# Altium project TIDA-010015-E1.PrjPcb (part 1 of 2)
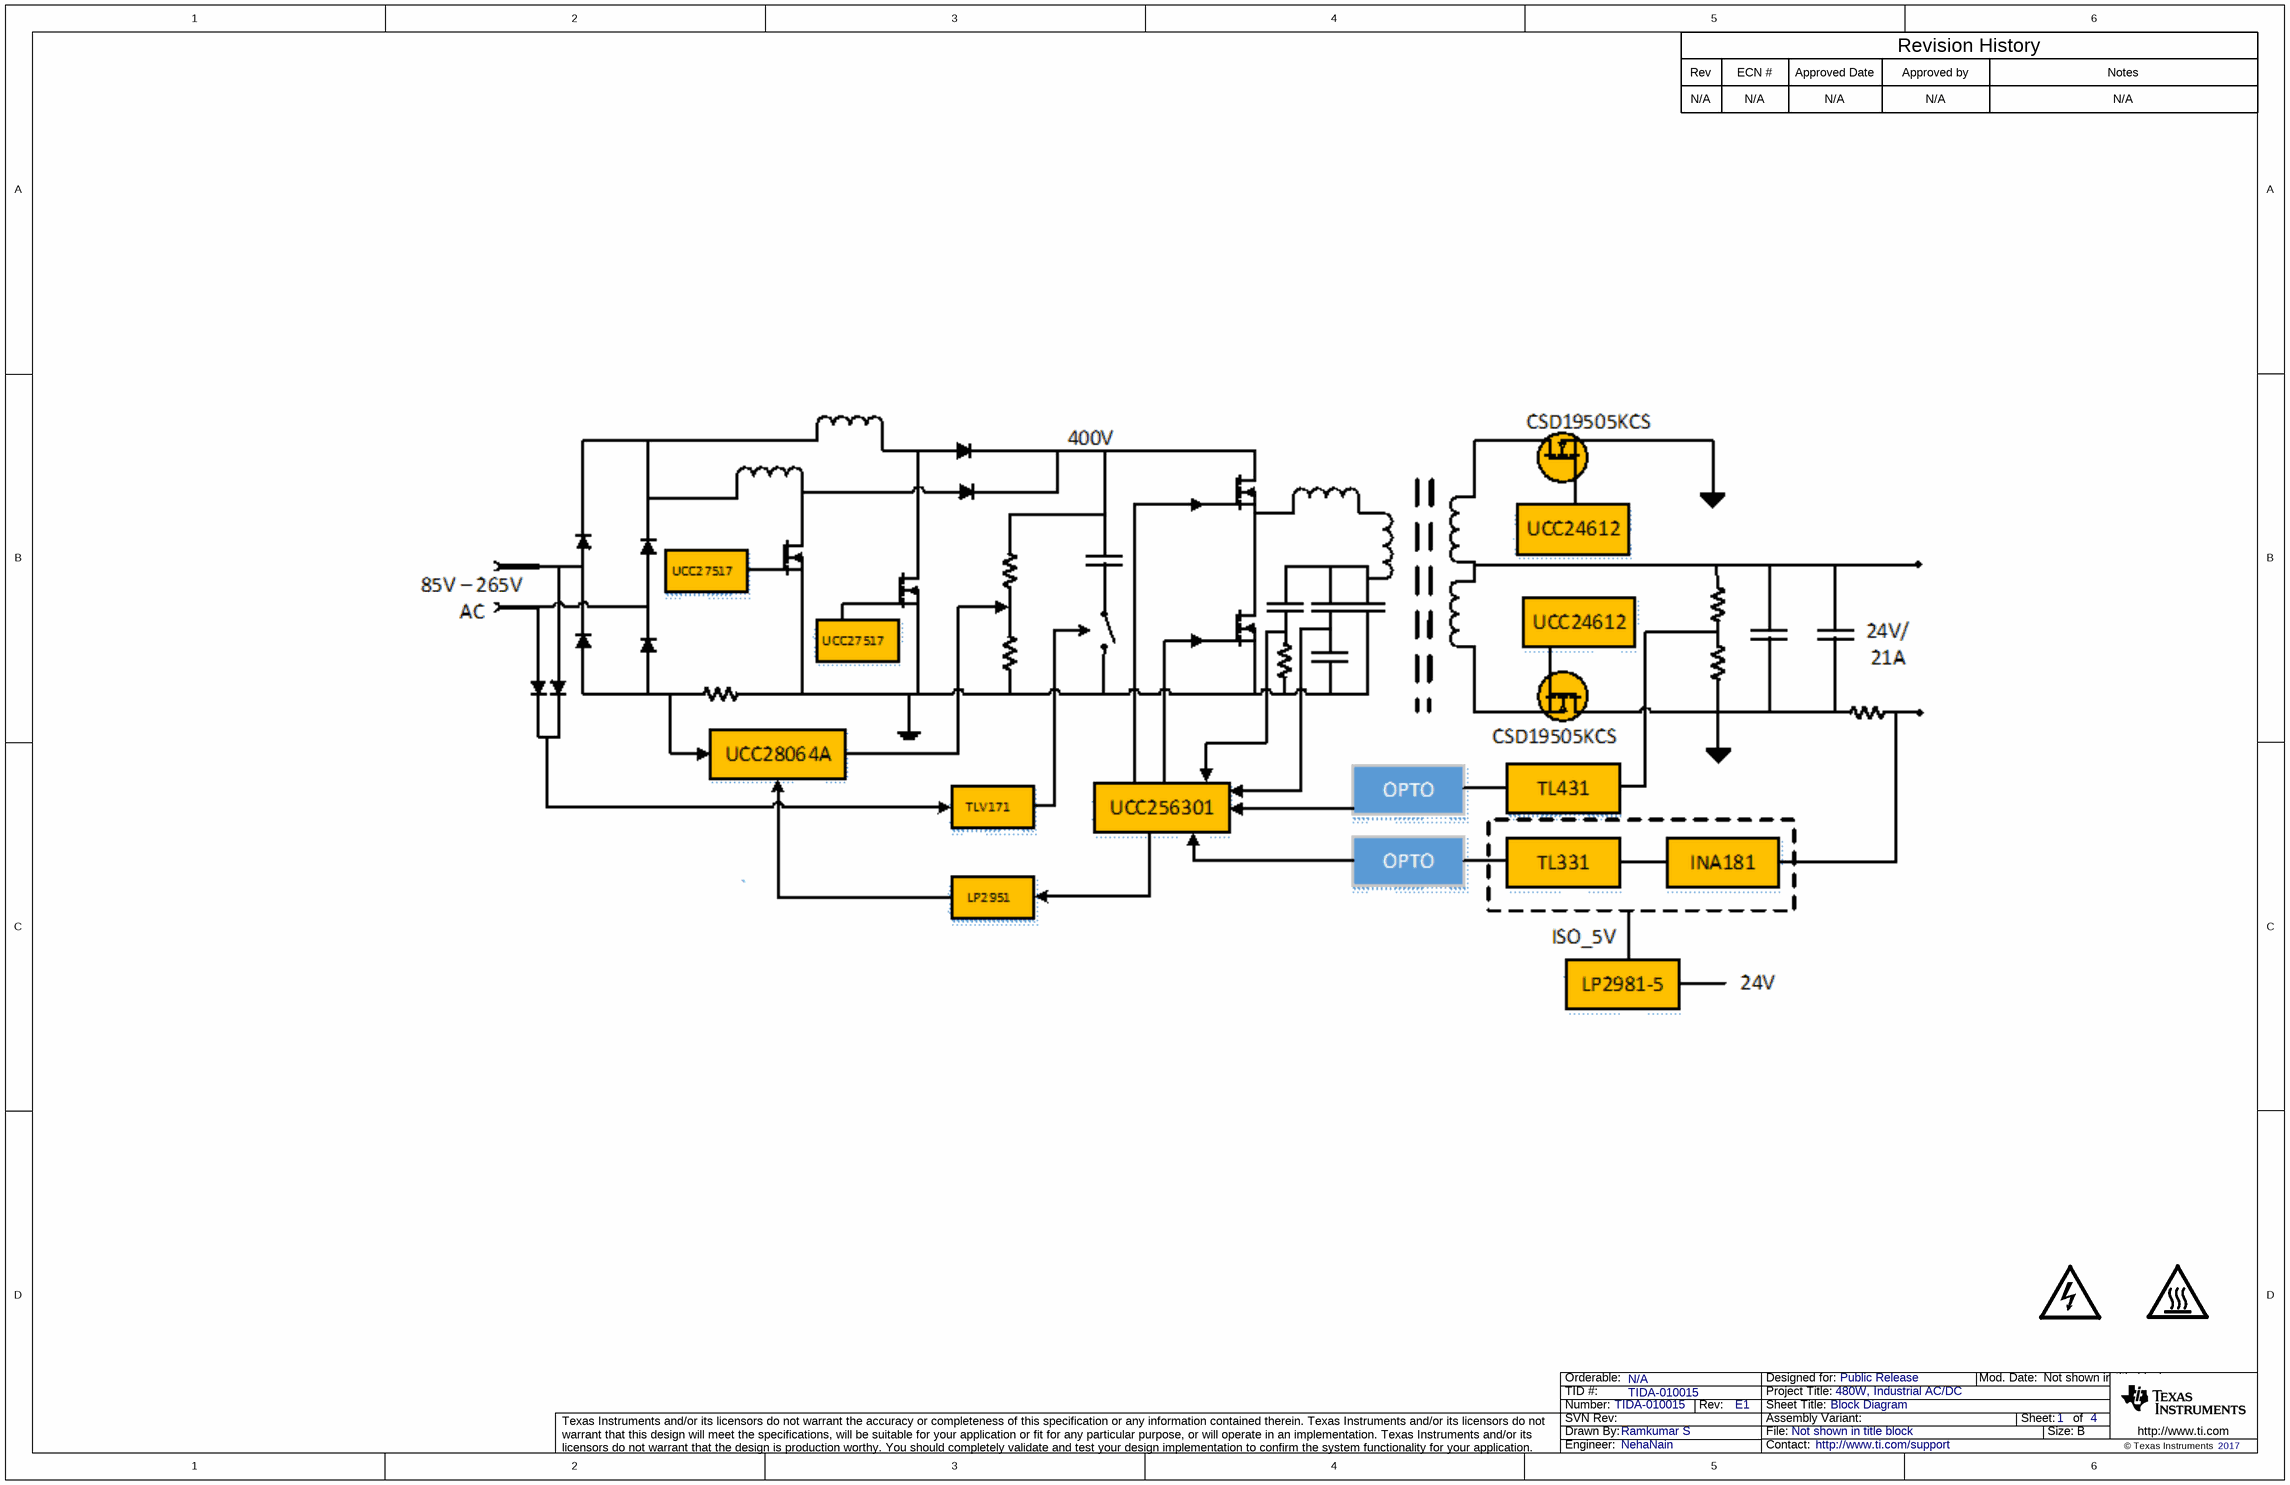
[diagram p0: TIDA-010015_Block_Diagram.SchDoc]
CopyrightYear: 2017; EVM_orderable: N/A; PCB_Layout: Koteswara Rao; PCB_Rev: E1; PRJ_Customer: Public Release; PRJ_Engineer: NehaNain; PRJ_Number: TIDA-010015; PRJ_Title: 480W, Industrial AC/DC; SCH_Rev: E1; TechSupport: http://www.ti.com/support; TID: TIDA-010015
4 sheets, 240 parts. Net scope: global (net labels, ports and power ports of the same name join across sheets).
Board file: TIDA-010015_PCB.PcbDoc
Sheets:
  TIDA-010015_Block_Diagram.SchDoc
  TIDA-010015_PFC.SchDoc
  TIDA-010015-LLC.SchDoc
  TIDA-010015_Hardware.SchDoc

## Sheet TIDA-010015_Block_Diagram.SchDoc: Block Diagram
size 431 x 279 mm; Date: Not shown in title block; ApprovedBy: Not shown in title block; CheckedBy: Not shown in title block; Author: Not shown in title block; CompanyName: Not shown in title block; DrawnBy: Ramkumar S; Engineer: Ramkumar S; Organization: Not shown in title block; Address1: Not shown in title block; Address2: Not shown in title block; Address3: Not shown in title block; Address4: Not shown in title block; DocumentNumber: 1; Revision: Use project parameter SCH_Rev; SheetNumber: 1; SheetTotal: 4; PageSetup: Record=PageOptions¦CenterHorizontal=True¦CenterVertical=True¦PrintScale=1.00¦XCorrection=1.00¦YCorrection=1.00¦PrintKind=0¦BorderSize=5000000¦LeftOffset=0¦BottomOffset=0¦Orientation=2¦PaperLength=1000¦PaperWidth=1000¦Scale=100¦PaperSource=15¦PrintQuality=600¦MediaType=1¦DitherType=10¦PaperKind=Letter¦PrintScaleMode=1

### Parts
(Parts that share a designator on the sheet are numbered #1, #2 ... from top to bottom, then left to right.)
LOGO?#1  DANGER HIGH VOLTAGE  [IEC_HighVoltage_Small]  (value not drawn)  (graphical)
LOGO?#2  CAUTION HOT SURFACE  [IEC_HotSurface_Small]  (value not drawn)  (graphical)

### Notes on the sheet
- Rev
- N/A
- ECN #
- Approved Date
- Approved by
- Revision History
- Notes

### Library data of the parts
LOGO?#1 = IEC_HighVoltage: IEC 61010-1 High Voltage Warning; SymbolCreator: a0412235
LOGO?#2 = IEC_HotSurface: IEC 61010-1 Hot Surface Warning; SymbolCreator: a0412235

## Sheet TIDA-010015_PFC.SchDoc: PFC
size 431 x 279 mm; Date: Not shown in title block; ApprovedBy: Not shown in title block; CheckedBy: Not shown in title block; Author: Not shown in title block; CompanyName: Not shown in title block; DrawnBy: Ramkumar S; Engineer: Ramkumar S; Organization: Not shown in title block; Address1: Not shown in title block; Address2: Not shown in title block; Address3: Not shown in title block; Address4: Not shown in title block; DocumentNumber: 1; Revision: Use project parameter SCH_Rev; SheetNumber: 2; SheetTotal: 4; PageSetup: Record=PageOptions¦CenterHorizontal=True¦CenterVertical=True¦PrintScale=1.00¦XCorrection=1.00¦YCorrection=1.00¦PrintKind=0¦BorderSize=5000000¦LeftOffset=0¦BottomOffset=0¦Orientation=2¦PaperLength=1000¦PaperWidth=1000¦Scale=100¦PaperSource=15¦PrintQuality=600¦MediaType=1¦DitherType=10¦PaperKind=Letter¦PrintScaleMode=1
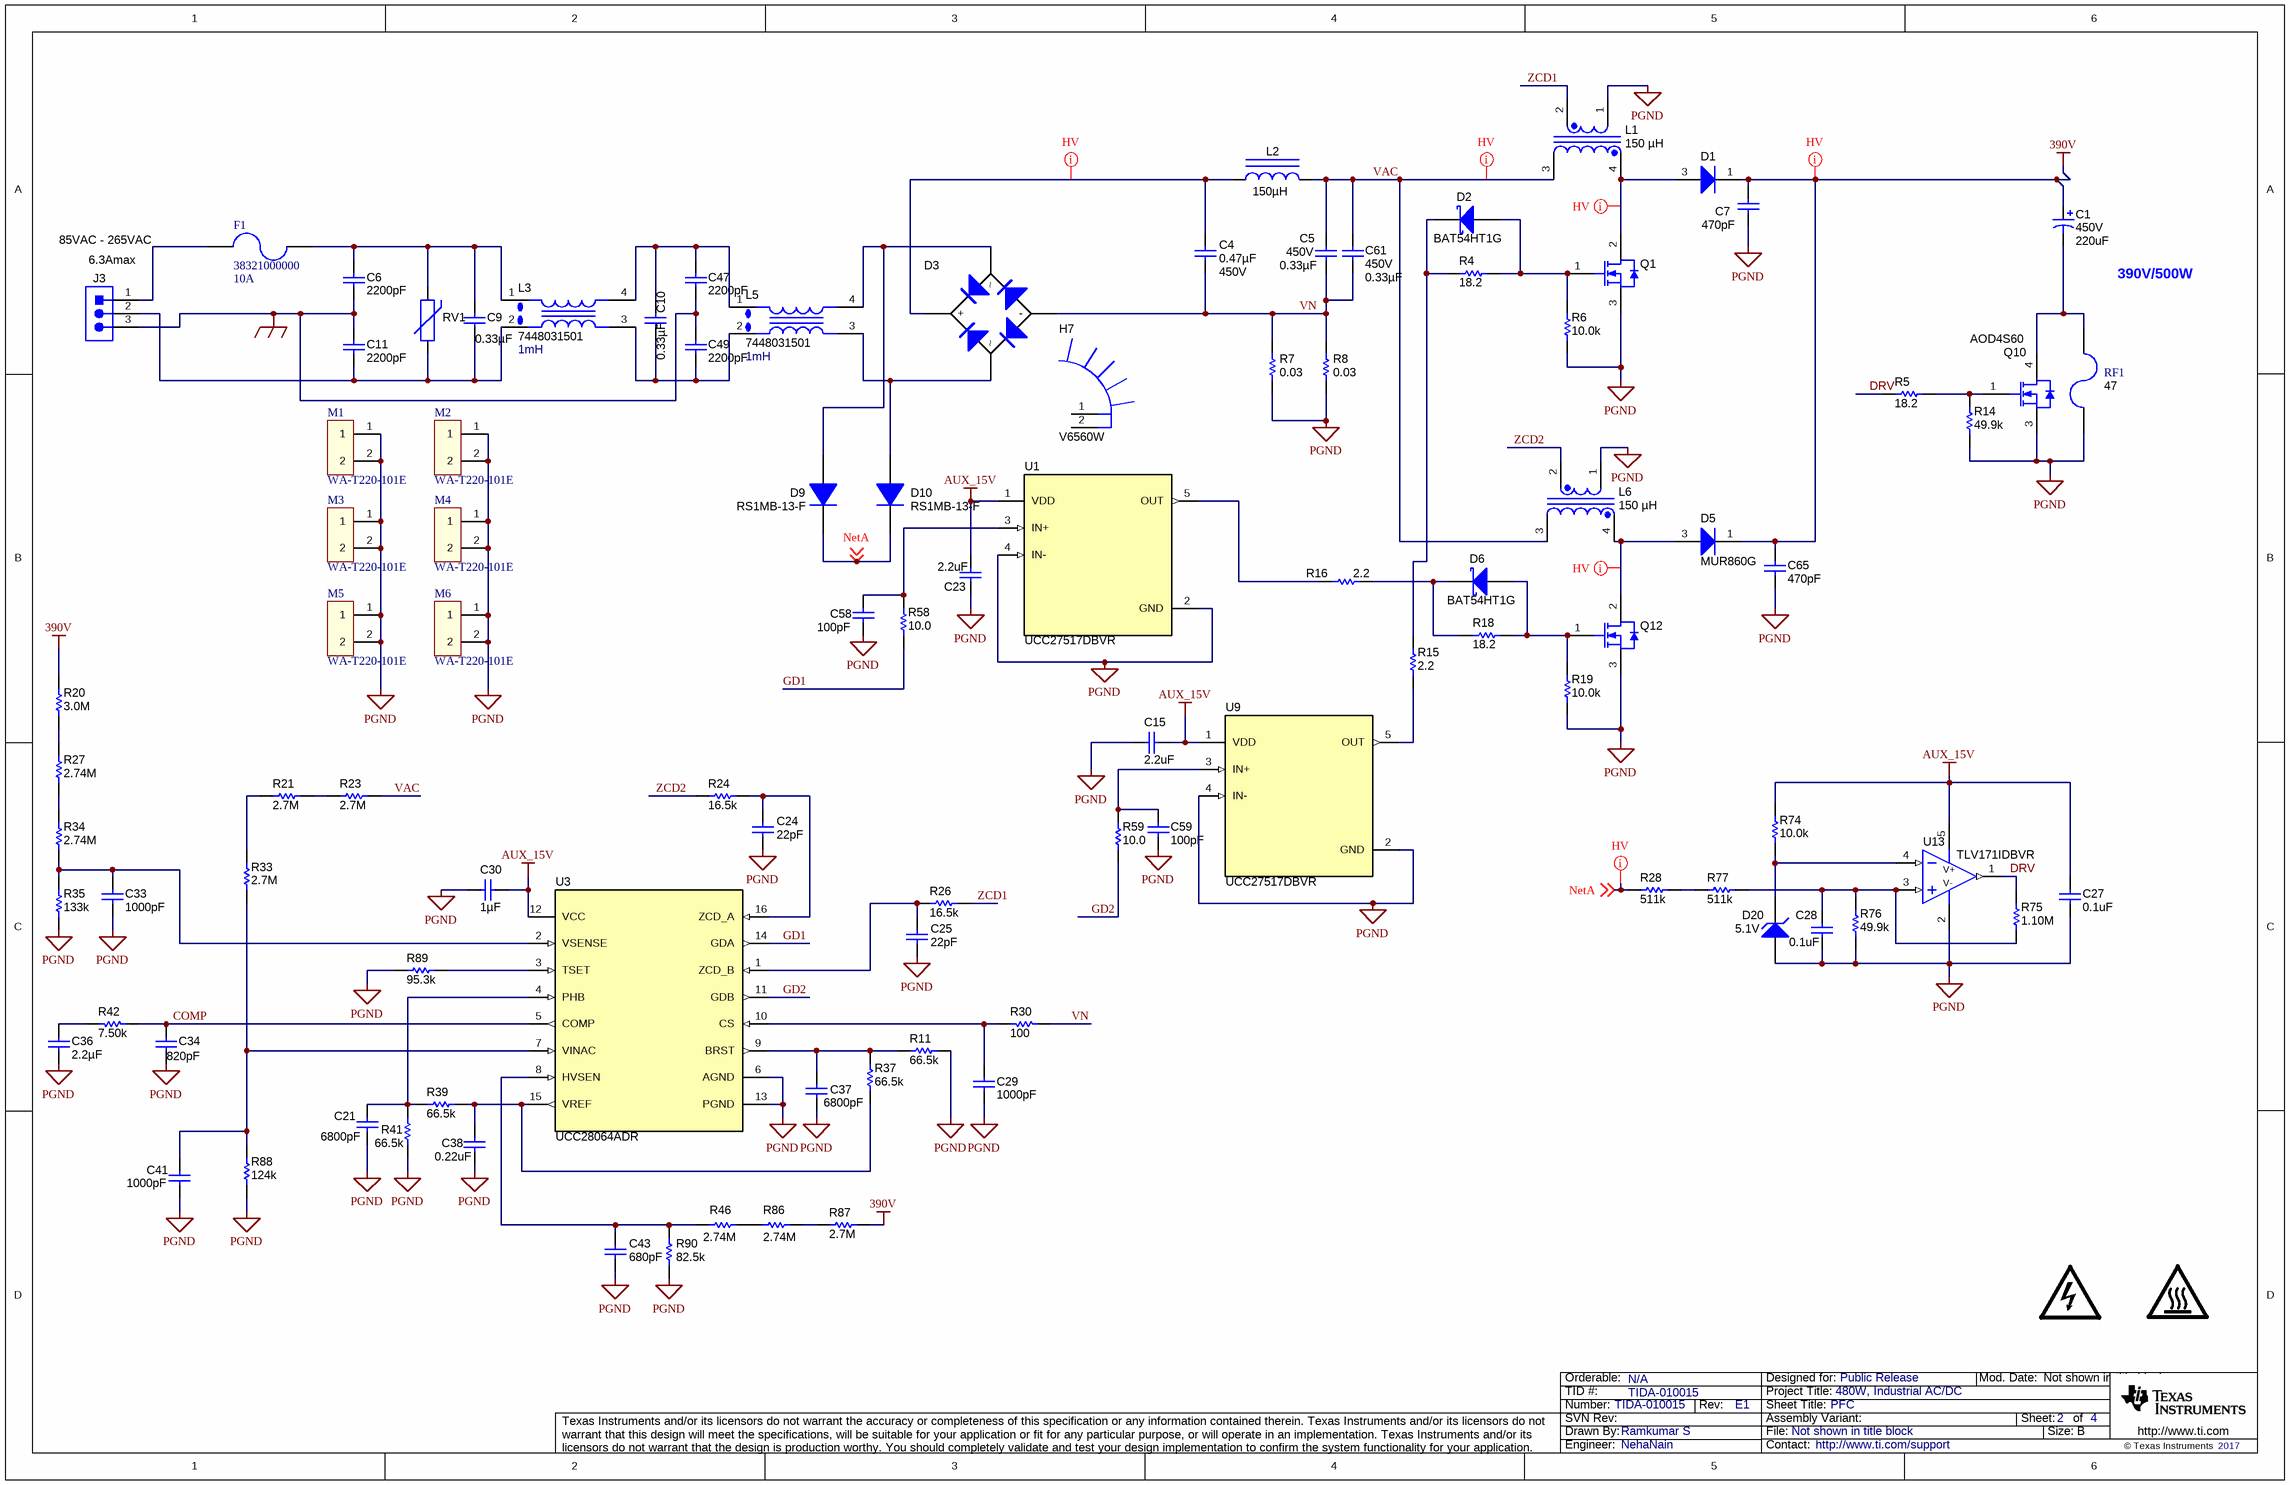
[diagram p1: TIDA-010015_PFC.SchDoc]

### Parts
(Parts that share a designator on the sheet are numbered #1, #2 ... from top to bottom, then left to right.)
C1  VDC_V: 450V  ValueDisplayed: 220uF  [SMQ_2540x2500]  (hidden comment: ESMR451VSN221MQ30S)
C4  ValueDisplayed: 0.47µF  Value2: 450V  [MPK_1800x650]  (hidden comment: 450MPK474J)
C5  VDC_V: 450V  ValueDisplayed: 0.33µF  [R46_1300x1200x600]  (hidden comment: ECW-FE2W334K)
C6  ValueDisplayed: 2200pF  [CD45_700x600x1100]  (hidden comment: AY2222M35Y5US63L7)
C7  ValueDisplayed: 470pF  [1210]  (hidden comment: VJ1210Y471KXEAT5Z)
C9  ValueDisplayed: 0.33µF  [B32922_14.5mm]  (hidden comment: B32922C3334K)
C10  ValueDisplayed: 0.33µF  [B32922_14.5mm]  (hidden comment: B32922C3334K)
C11  ValueDisplayed: 2200pF  [CD45_700x600x1100]  (hidden comment: AY2222M35Y5US63L7)
C15  ValueDisplayed: 2.2uF  [0805_150]  (hidden comment: 08053C225KAT2A)
C21  ValueDisplayed: 6800pF  [0603]  (hidden comment: GRM188R71E682KA01D)
C23  ValueDisplayed: 2.2uF  [0805_150]  (hidden comment: 08053C225KAT2A)
C24  ValueDisplayed: 22pF  [0603]  (hidden comment: C0603C220J5GACTU)
C25  ValueDisplayed: 22pF  [0603]  (hidden comment: C0603C220J5GACTU)
C27  ValueDisplayed: 0.1uF  [0603]  (hidden comment: C0603C104J3RACTU)
C28  ValueDisplayed: 0.1uF  [0603]  (hidden comment: C0603C104J3RACTU)
C29  ValueDisplayed: 1000pF  [0603]  (hidden comment: C1608X7R1H102K)
C30  ValueDisplayed: 1µF  [0603]  (hidden comment: GRM188R71E105KA12D)
C33  ValueDisplayed: 1000pF  [0603]  (hidden comment: C1608X7R1H102K)
C34  ValueDisplayed: 820pF  [0603]  (hidden comment: 06035A821JAT2A)
C36  ValueDisplayed: 2.2µF  [0805_HV]  (hidden comment: 0805YD225KAT2A)
C37  ValueDisplayed: 6800pF  [0603]  (hidden comment: GRM188R71E682KA01D)
C38  ValueDisplayed: 0.22uF  [0603]  (hidden comment: GRM188R71H224KAC4D)
C41  ValueDisplayed: 1000pF  [0603]  (hidden comment: 06031C102MAT2A)
C43  ValueDisplayed: 680pF  [0603]  (hidden comment: GRM188R71H681KA01D)
C47  ValueDisplayed: 2200pF  [CD45_700x600x1100]  (hidden comment: AY2222M35Y5US63L7)
C49  ValueDisplayed: 2200pF  [CD45_700x600x1100]  (hidden comment: AY2222M35Y5US63L7)
C58  ValueDisplayed: 100pF  [0805_HV1]  (hidden comment: 08055A101JAT2A)
C59  ValueDisplayed: 100pF  [0805_HV1]  (hidden comment: 08055A101JAT2A)
C61  VDC_V: 450V  ValueDisplayed: 0.33µF  [R46_1300x1200x600]  (hidden comment: ECW-FE2W334K)
C65  ValueDisplayed: 470pF  [1210]  (hidden comment: VJ1210Y471KXEAT5Z)
D1  MUR860G  [TO-220AC]  (value not drawn)
D2  BAT54HT1G  [sod-323]
D3  GBU2510-G  [GBU]  (value not drawn)
D5  MUR860G  [TO-220AC]
D6  BAT54HT1G  [sod-323]
D9  RS1MB-13-F  [SMB]
D10  RS1MB-13-F  [SMB]
D20  value 5.1V  [SOD-323]  (hidden comment: BZT52C5V1S-7-F)
F1  38321000000  value 10A  [FUSE_38321000000]
H7  V6560W  [ASMN_V6560X]
J3  350429-1  [TE_350429-1]  (value not drawn)
L1  value 150 µH  [IND_PQ2625]  (hidden comment: Custom)
L2  ValueDisplayed: 150µH  [IND_7447076]  (hidden comment: 7447076)
L3  7448031501  value 1mH  [WURTH_7448031501]
L5  7448031501  value 1mH  [WURTH_7448031501]
L6  value 150 µH  [IND_PQ2625]  (hidden comment: Custom)
LOGO?#3  DANGER HIGH VOLTAGE  [IEC_HighVoltage_Small]  (value not drawn)  (graphical)
LOGO?#4  CAUTION HOT SURFACE  [IEC_HotSurface_Small]  (value not drawn)  (graphical)
M1  WA-T220-101E  [HEATSINK_WA-T220-101E]
M2  WA-T220-101E  [HEATSINK_WA-T220-101E]
M3  WA-T220-101E  [HEATSINK_WA-T220-101E]
M4  WA-T220-101E  [HEATSINK_WA-T220-101E]
M5  WA-T220-101E  [HEATSINK_WA-T220-101E]
M6  WA-T220-101E  [HEATSINK_WA-T220-101E]
Q1  IPP60R190P6  [TO-220AB]  (value not drawn)
Q10  AOD4S60  [DPAK]
Q12  IPP60R190P6  [TO-220AB]  (value not drawn)
R4  ValueDisplayed: 18.2  [0805_HV1]  (hidden comment: CRCW080518R2FKEA)
R5  ValueDisplayed: 18.2  [0805_HV1]  (hidden comment: CRCW080518R2FKEA)
R6  ValueDisplayed: 10.0k  [0805_HV]  (hidden comment: CRCW080510K0FKEA)
R7  ValueDisplayed: 0.03  [2512]  (hidden comment: CSRN2512FK30L0)
R8  ValueDisplayed: 0.03  [2512]  (hidden comment: CSRN2512FK30L0)
R11  ValueDisplayed: 66.5k  [0603]  (hidden comment: CRCW060366K5FKEA)
R14  ValueDisplayed: 49.9k  [0603]  (hidden comment: ERJ-3EKF4992V)
R15  ValueDisplayed: 2.2  [0805_HV1]  (hidden comment: CRCW08052R20JNEA)
R16  ValueDisplayed: 2.2  [0805_HV1]  (hidden comment: CRCW08052R20JNEA)
R18  ValueDisplayed: 18.2  [0805_HV1]  (hidden comment: CRCW080518R2FKEA)
R19  ValueDisplayed: 10.0k  [0805_HV]  (hidden comment: CRCW080510K0FKEA)
R20  ValueDisplayed: 3.0M  [1206]  (hidden comment: CRCW12063M00JNEA)
R21  ValueDisplayed: 2.7M  [1206]  (hidden comment: CRCW12062M70JNEA)
R23  ValueDisplayed: 2.7M  [1206]  (hidden comment: CRCW12062M70JNEA)
R24  ValueDisplayed: 16.5k  [0603]  (hidden comment: CRCW060316K5FKEA)
R26  ValueDisplayed: 16.5k  [0603]  (hidden comment: CRCW060316K5FKEA)
R27  ValueDisplayed: 2.74M  [0805_HV]  (hidden comment: CRCW08052M74FKEA)
R28  value 511k  [1206]  (hidden comment: CRCW1206511KFKEA)
R30  ValueDisplayed: 100  [0603]  (hidden comment: CRCW0603100RFKEA)
R33  ValueDisplayed: 2.7M  [1206]  (hidden comment: CRCW12062M70JNEA)
R34  ValueDisplayed: 2.74M  [0805_HV]  (hidden comment: CRCW08052M74FKEA)
R35  ValueDisplayed: 133k  [0603]  (hidden comment: CRCW0603133KFKEA)
R37  ValueDisplayed: 66.5k  [0603]  (hidden comment: CRCW060366K5FKEA)
R39  ValueDisplayed: 66.5k  [0603]  (hidden comment: CRCW060366K5FKEA)
R41  ValueDisplayed: 66.5k  [0603]  (hidden comment: CRCW060366K5FKEA)
R42  ValueDisplayed: 7.50k  [0603]  (hidden comment: CRCW06037K50FKEA)
R46  ValueDisplayed: 2.74M  [0805_HV]  (hidden comment: CRCW08052M74FKEA)
R58  ValueDisplayed: 10.0  [0603]  (hidden comment: CRCW060310R0FKEAHP)
R59  ValueDisplayed: 10.0  [0603]  (hidden comment: CRCW060310R0FKEAHP)
R74  ValueDisplayed: 10.0k  [0805_HV]  (hidden comment: CRCW080510K0FKEA)
R75  ValueDisplayed: 1.10M  [0603]  (hidden comment: CRCW06031M10FKEA)
R76  value 49.9k  [1206]  (hidden comment: CRCW120649K9FKEA)
R77  value 511k  [1206]  (hidden comment: CRCW1206511KFKEA)
R86  ValueDisplayed: 2.74M  [0805_HV]  (hidden comment: CRCW08052M74FKEA)
R87  ValueDisplayed: 2.7M  [1206]  (hidden comment: CRCW12062M70JNEA)
R88  ValueDisplayed: 124k  [0603]  (hidden comment: ERJ-3EKF1243V)
R89  ValueDisplayed: 95.3k  [0603]  (hidden comment: CRCW060395K3FKEA)
R90  ValueDisplayed: 82.5k  [0603]  (hidden comment: CRCW060382K5FKEA)
RF1  ValueDisplayed: 47  [RESADV550W80L2600D750B]  (hidden comment: EMC2-47RKI)
RV1  S10K275E2  [VAR_S10K275E2]  (value not drawn)
U1  UCC27517DBVR  [DBV0005A_N]
U3  PartNumber: UCC28064ADR  [D0016A_N]  (hidden comment: UCC28064DR)
U9  UCC27517DBVR  [DBV0005A_N]
U13  TLV171IDBVR  [DBV0005A_N]

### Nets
390V: C1.1(+) C7.1 C65.1 D1.1(K) D5.1(K) R20.2 R87.2
AUX_15V: C15.2 C23.1 C27.1 C30.2 R74.2 U1.1(VDD) U3.12(VCC) U9.1(VDD) U13.5(V+)
EARTH: C6.2 C11.1 C47.2 C49.1 J3.3
PGND: C7.2 C15.1 C21.2 C23.2 C24.2 C25.2 C27.2 C28.2 C29.2 C30.1 C33.2 C34.2 C36.2 C37.2 C38.2 C41.2 C43.2 C58.2 C59.2 C65.2 D20.2(A) L1.1 L6.1 M1.1 M1.2 M2.1 M2.2 M3.1 M3.2 M4.1 M4.2 M5.1 M5.2 M6.1 M6.2 Q1.3(S) Q10.3(S) Q12.3(S) R6.1 R7.1 R8.1 R11.2 R14.2 R19.1 R35.1 R41.2 R76.1 R88.2 R89.1 R90.1 RF1.1 U1.2(GND) U1.4(IN-) U3.6(AGND) U3.13(PGND) U9.2(GND) U9.4(IN-) U13.2(V-)
COMP: C34.1 R42.1 U3.5(COMP)
DRV: R5.2 R75.2 U13.1(OUT)
GD1: R58.1 U3.14(GDA)
GD2: R59.1 U3.11(GDB)
NetA: D9.1(K) D10.1(K) R28.1 ; off-sheet NetA
VAC: C5.1 C61.1 L1.3 L2.2 L6.3 R23.2
VN: C4.2 C5.2 C61.2 D3.4(-) R7.2 R8.2 R30.1
ZCD1: L1.2 R26.2
ZCD2: L6.2 R24.1
NetC1_2: C1.2(-) Q10.4(D) RF1.2
NetC4_1: C4.1 D3.1(+) L2.1
NetC6_1: C6.1 C9.1 F1.2 L3.1 RV1.2
NetC9_2: C9.2 C11.2 J3.2 L3.2 RV1.1
NetC10_1: C10.1 C47.1 L3.4 L5.1
NetC10_2: C10.2 C49.2 L3.3 L5.2
NetC21_1: C21.1 R39.1 R41.1 U3.4(PHB)
NetC24_1: C24.1 R24.2 U3.16(ZCD_A)
NetC25_1: C25.1 R26.1 U3.1(ZCD_B)
NetC28_1: C28.1 R75.1 R76.2 R77.2 U13.3(IN+)
NetC29_1: C29.1 R30.2 U3.10(CS)
NetC33_1: C33.1 R34.1 R35.2 U3.2(VSENSE)
NetC36_1: C36.1 R42.2
NetC37_1: C37.1 R11.1 R37.2 U3.9(BRST)
NetC38_1: C38.1 R37.1 R39.2 U3.15(VREF)
NetC41_1: C41.1 R33.2 R88.1 U3.7(VINAC)
NetC43_1: C43.1 R46.1 R90.2 U3.8(HVSEN)
NetC58_1: C58.1 R58.2 U1.3(IN+)
NetC59_1: C59.1 R59.2 U9.3(IN+)
NetD1_3: D1.3(A) L1.4 Q1.2(D)
NetD2_1: D2.1(K) R4.1 R15.2
NetD2_2: D2.2(A) Q1.1(G) R4.2 R6.2
NetD3_2: D3.2 D9.2(A) L5.4
NetD3_3: D3.3 D10.2(A) L5.3
NetD5_3: D5.3(A) L6.4 Q12.2(D)
NetD6_1: D6.1(K) R16.2 R18.1
NetD6_2: D6.2(A) Q12.1(G) R18.2 R19.2
NetD20_1: D20.1(K) R74.1 U13.4(IN-)
NetF1_1: F1.1 J3.1
NetQ10_1: Q10.1(G) R5.1 R14.1
NetR15_1: R15.1 U9.5(OUT)
NetR16_1: R16.1 U1.5(OUT)
NetR20_1: R20.1 R27.2
NetR21_1: R21.1 R33.1
NetR21_2: R21.2 R23.1
NetR27_1: R27.1 R34.2
NetR28_2: R28.2 R77.1
NetR46_2: R46.2 R86.1
NetR86_2: R86.2 R87.1
NetR89_2: R89.2 U3.3(TSET)

Not connected (* = marked no-connect by the designer): H7 1 2

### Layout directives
net class HV: 390V, NetA, NetC4_1, NetD1_3, NetD5_3, VAC

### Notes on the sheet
- 85VAC - 265VAC
- (near J3) 6.3Amax
- 390V/500W

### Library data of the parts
C1 = CMP-0010055-2: CAP ALUM 220UF 20% 450V SNAP; Manufacturer: Chemi-Con; TaMin_C: -25°C; Polarized: Y; Value1: Unknown; U/M: EA; TaMax_C: 85°C; SizeZ_mm: 27; SizeX_mm: 25.4; Cap_Case: 25.4x25mm; CompType: Capacitor; Cap_F: 220µF
C4 = 450MPK474J: CAP, Film, 0.47 µF, 450 V, +/- 5%, TH; Manufacturer: Rubycon; Polarized: N; CompType: Capacitor; Value: 0.47uF; U/M: EA; Cap_F: 0.00000047; Tolerance_%: 5; Value1: Unknown; VDC_V: 450; TaMin_C: -40; TaMax_C: 105; Cap_Case: 18x6.5mm; AEC Category: Q200
C5 C61 = CMP-0012558-3: 0.33µF Film Capacitor 450V Polypropylene (PP), Metallized Radial; Manufacturer: Panasonic Electronic Components; TaMin_C: -40°C; Polarized: N; SizeAreaWB_mm2: 120; Value1: Unknown; TaMax_C: 110°C; Tolerance_%: 10%; SizeZ_mm: 12.1; SizeX_mm: 13; SizeY_mm: 6; Cap_Case: 13x12x6; SizeArea_mm2: 78; AEC Category: Q200
C6 C11 C47 C49 = AY2222M35Y5US63L7: CAP, CERM, 2200 pF, 300 V, +/- 20%, Y5U, AEC-Q200 Grade 1, D9.5xT5mm; Manufacturer: Vishay-Bccomponents; Polarized: N; CompType: Capacitor; Value: 2200pF; U/M: EA; Cap_F: 0.0000000022; Tolerance_%: 20; Value1: Unknown; VDC_V: 300; Value2: 300V; TaMin_C: -55; TaMax_C: 125; Cap_Case: 9.5x5mm; SizeArea_mm2: 47.5; SizeAreaWB_mm2: 80.5; SizeX_mm: 9.5; SizeY_mm: 5; SizeZ_mm: 14.5; AEC Category: Q200; AEC Qualified: Y; AEC Grade: 1
C7 C65 = VJ1210Y471KXEAT5Z: CAP, CERM, 470 pF, 500 V, +/- 10%, X7R, 1210; Manufacturer: Vishay-Vitramon; Polarized: N; CompType: Capacitor; Value: 470pF; U/M: EA; Cap_F: 0.00000000047; Tolerance_%: 10; Value1: Unknown; VDC_V: 500; Value2: 500V; TaMin_C: -55; TaMax_C: 125; SizeArea_mm2: 8; SizeAreaWB_mm2: 14.7; SizeX_mm: 3.2; SizeY_mm: 2.5; SizeZ_mm: 1.35; AEC Category: Q200
C9 C10 = B32922C3334K: CAP, Film, 0.33 µF, X2 305 VAC, +/- 10%, TH; Manufacturer: TDK; Polarized: N; CompType: Capacitor; Value: 0.33uF; U/M: EA; Cap_F: 0.00000033; Tolerance_%: 10; TaMin_C: -40; TaMax_C: 110; Cap_Case: 18x8x14.5mm; SizeAreaWB_mm2: 210; SizeArea_mm2: 153; SizeX_mm: 18; SizeY_mm: 8.5; SizeZ_mm: 14.5; AEC Category: Q200; VAC_X: 305
C15 C23 = CMP-0007573-2: CAP, CERM, 2.2 uF, 25 V, +/- 10%, X7R, 0805; Manufacturer: AVX; TaMin_C: -55°C; Polarized: N; SizeAreaWB_mm2: 6.75; Value1: Unknown; U/M: EA; Value: 2.2uF; TaMax_C: 125°C; SizeZ_mm: 1.5; SizeX_mm: 2; SizeY_mm: 1.25; Cap_Case: 0805; Value2: 25V; SizeArea_mm2: 2.5; CompType: Capacitor; Cap_F: 2.2µF; AEC Category: Q200
C21 C37 = CMP-0007427-4: CAP, CERM, 6800 pF, 25 V, +/- 10%, X7R, 0603; Manufacturer: MuRata; TaMin_C: -55°C; Polarized: N; SizeAreaWB_mm2: 4.68; Value1: Unknown; U/M: EA; Value: 6800pF; TaMax_C: 125°C; SizeZ_mm: 1; SizeX_mm: 1.6; SizeY_mm: 0.8; Value2: 25V; SizeArea_mm2: 1.28; CompType: Capacitor; Cap_F: 6.8nF; AEC Category: Q200
C24 C25 = C0603C220J5GACTU: CAP, CERM, 22 pF, 50 V, +/- 5%, C0G/NP0, 0603; Manufacturer: Kemet; Polarized: N; CompType: Capacitor; Value: 22pF; U/M: EA; Cap_F: 0.000000000022; Tolerance_%: 5; Value1: Unknown; VDC_V: 50; Value2: 50V; TaMin_C: -55; TaMax_C: 125
C27 C28 = CMP-0006856-5: CAP, CERM, 0.1 uF, 25 V, +/- 5%, X7R, 0603; Manufacturer: Kemet; TaMin_C: -55°C; Polarized: N; SizeAreaWB_mm2: 4.68; Value1: Unknown; U/M: EA; Value: 0.1uF; TaMax_C: 125°C; SizeZ_mm: 1; SizeX_mm: 1.6; SizeY_mm: 0.8; Value2: 25V; SizeArea_mm2: 1.28; CompType: Capacitor; Cap_F: 100nF; AEC Category: Q200
C29 C33 = C1608X7R1H102K: CAP, CERM, 1000 pF, 50 V, +/- 10%, X7R, 0603; Manufacturer: TDK; Polarized: N; CompType: Capacitor; Value: 1000pF; U/M: EA; Cap_F: 0.000000001; Tolerance_%: 10; ESR_ohm: 0.24; Value1: 0.24 ohm; VDC_V: 50; Value2: 50V; TaMin_C: -55; TaMax_C: 125
C30 = GRM188R71E105KA12D: CAP, CERM, 1 µF, 25 V, +/- 10%, X7R, 0603; Manufacturer: MuRata; Polarized: N; CompType: Capacitor; Value: 1uF; U/M: EA; Cap_F: 0.000001; Tolerance_%: 10; Value1: Unknown; VDC_V: 25; Value2: 25V; TaMin_C: -55; TaMax_C: 125
C34 = 06035A821JAT2A: CAP, CERM, 820 pF, 50 V, +/- 5%, C0G/NP0, 0603; Manufacturer: AVX; Polarized: N; CompType: Capacitor; Value: 820pF; U/M: EA; Cap_F: 0.00000000082; Tolerance_%: 5; ESR_ohm: 0.052; Value1: 0.052 ohm; VDC_V: 50; Value2: 50V; TaMin_C: -55; TaMax_C: 125
C36 = 0805YD225KAT2A: CAP, CERM, 2.2 µF, 16 V, +/- 10%, X5R, 0805; Manufacturer: AVX; Polarized: N; CompType: Capacitor; Value: 2.2uF; U/M: EA; Cap_F: 0.0000022; Tolerance_%: 10; ESR_ohm: 0.009; Value1: 0.009 ohm; VDC_V: 16; Value2: 16V; TaMin_C: -55; TaMax_C: 85; Cap_Case: 0805
C38 = CMP-0007445-4: CAP, CERM, 0.22 uF, 50 V, +/- 10%, X7R, 0603; Manufacturer: MuRata; TaMin_C: -55°C; Polarized: N; SizeAreaWB_mm2: 4.68; Value1: Unknown; U/M: EA; Value: 0.22uF; TaMax_C: 125°C; SizeZ_mm: 1; SizeX_mm: 1.6; SizeY_mm: 0.8; Value2: 50V; SizeArea_mm2: 1.28; CompType: Capacitor; Cap_F: 220nF; AEC Category: Q200
C41 = 06031C102MAT2A: CAP, CERM, 1000 pF, 100 V, +/- 20%, X7R, 0603; Manufacturer: AVX; Polarized: N; CompType: Capacitor; Value: 1000pF; U/M: EA; Cap_F: 0.000000001; Tolerance_%: 20; ESR_ohm: 0.276; Value1: 0.276 ohm; VDC_V: 100; Value2: 100V; TaMin_C: -55; TaMax_C: 125
C43 = GRM188R71H681KA01D: CAP, CERM, 680 pF, 50 V, +/- 10%, X7R, 0603; Manufacturer: MuRata; Polarized: N; CompType: Capacitor; Value: 680pF; U/M: EA; Cap_F: 0.00000000068; Tolerance_%: 10; Value1: Unknown; VDC_V: 50; Value2: 50V; TaMin_C: -55; TaMax_C: 125
C58 C59 = 08055A101JAT2A: CAP, CERM, 100 pF, 50 V,+/- 5%, C0G/NP0, 0805; Manufacturer: AVX; Polarized: N; CompType: Capacitor; Value: 100pF; U/M: EA; Cap_F: 0.0000000001; Tolerance_%: 5; ESR_ohm: 0.356; Value1: 0.356 ohm; VDC_V: 50; Value2: 50V; TaMin_C: -55; TaMax_C: 125; Cap_Case: 0805; SizeArea_mm2: 2.5; SizeAreaWB_mm2: 6.75; SizeX_mm: 2; SizeY_mm: 1.25; SizeZ_mm: 1.45; AEC Category: Q200; Green_Lifecycle: Active; Green_REACh: Passed
D1 D5 = CMP-0029037-1: Diode, Ultrafast, 600 V, 8 A, TH; Manufacturer: ON Semiconductor; Io_A: 8A; Green_Lifecycle: Not Set; SizeAreaWB_mm2: 78.975; Vr_V: 600V; Green_REACh: Incomplete; TJmax_C: 175°C; U/M: EA; Value: 600V; SizeZ_mm: 23; SizeX_mm: 10.15; SizeY_mm: 4.5; Vf_V: 9.8dV; Value2: 0.98V; SizeArea_mm2: 45.675; AEC Category: Q101; RJC_CperW: 4.75
D2 D6 = BAT54HT1G: Diode, Schottky, 30V, 0.2A, SOD-323; Manufacturer: ON Semiconductor; Value: 0.35V; U/M: EA; Vf_V: 0.35; Io_A: 0.2; Vr_V: 30
D3 = GBU4A-BP: RECT BRIDGE GPP 1000V 25A GBU; Manufacturer: Comchip Technology; CompType: Diode; U/M: EA; Vf_V: 0.95; Io_A: 4; Value1: 8A; Vr_V: 50; Value2: 50V; TJmax_C: 150; RJC_CperW: 2.2; Type: Switching-Bridge
D9 D10 = RS1MB-13-F: Diode, P-N, 1000 V, 1 A, SMB; Manufacturer: Diodes Inc.; U/M: EA; Vf_V: 1.3; Value: 1000V; Value1: 1A; Value2: 1.3V; Io_A: 1; Vr_V: 1000; TJmax_C: 150; RJC_CperW: 20; SizeAreaWB_mm2: 44.156; SizeArea_mm2: 21.336; SizeX_mm: 5.6; SizeY_mm: 3.81; SizeZ_mm: 2.6; AEC Category: Q101; Green_Lifecycle: Active; Green_REACh: Passed
D20 = CMP-0005865-1: Diode, Zener, 5.1 V, 200 mW, SOD-323; Manufacturer: Diodes Inc.; Power_W: 200mW; SizeAreaWB_mm2: 8.695; Value1: 0.2W; RJA_CperW: 625; U/M: EA; SizeZ_mm: 1; SizeX_mm: 2.7; SizeY_mm: 1.35; SizeArea_mm2: 3.645; AEC Category: Q101
F1 = 38321000000: FUSE, BOARD MOUNT, 10 A, 300 V, TH-2P; Manufacturer: LITTELFUSE INC; SymbolCreator: x0199378
H7 = CMP-0004065-1: HEATSINK, ALUM, ANOD, for TO-220; Manufacturer: Assman WSW
J3 = 350429-1: Header(Shrouded), 6.35mm, 3x1, Tin, TH; Manufacturer: TE Connectivity; SymbolCreator: a0799628; U/M: EA
L1 L6 = PFC4124QM-161K06D-00: Transformer, 160 uH, TH; SymbolCreator: Altium; U/M: EA
L2 = 7447020: Inductor, Toroid, Powdered Iron, 150 µH, 5A, TH; Manufacturer: Wurth Elektronik; Value: 150uH; Value1: 0.16 ohm
L3 L5 = 7448031501: FILTER, WE-CMBNC COMMON MODE POWER LINE CHOKE, 1mH, 15A, VERTICAL, TH-4P; Manufacturer: Wurth Elektronics; SymbolCreator: x0199378
LOGO?#3 = IEC_HighVoltage: as LOGO?#1 on sheet TIDA-010015_Block_Diagram
LOGO?#4 = IEC_HotSurface: as LOGO?#2 on sheet TIDA-010015_Block_Diagram
M1-M6 = WA-T220-101E: HEATSINK, ALUMINIUM WITH CLIP, VERTICAL MOUNT, SOLDERABLE PIN, TO-220; Manufacturer: OHMITE; SymbolCreator: x0199378
Q1 Q12 = CMP-0001223-3: MOSFET N-CHANNEL 600V 26A TO220; PartNumber: IPA60R120P7XKSA1; Alternate Manufacturer: None; Manufacturer: Infineon Technologies; SizeZ_mm: 19.4; ChType: N; Value2: 37 nC; VdsMax_V: 650V; SizeX_mm: 10.2; SizeY_mm: 4.5; Vgs_V: 20V; QgTyp_nC: 37; Value: 650V; SizeArea_mm2: 45.9; AEC Category: Q101; IdsMax_A: 20.2A; SizeAreaWB_mm2: 79.3; U/M: EA
Q10 = CMP-0001138-3: MOSFET, N-CH, 600 V, 4 A, DPAK; Alternate Manufacturer: None; Manufacturer: AOS; SizeZ_mm: 2.29; ChType: N; Value2: 6 nC; VdsMax_V: 600V; SizeX_mm: 9.91; SizeAreaWB_mm2: 101.7114; SizeY_mm: 6.54; Vgs_V: 30V; QgTyp_nC: 6; Value: 600V; SizeArea_mm2: 64.8114; AEC Category: Q101; IdsMax_A: 4A; U/M: EA
R4 R5 R18 = CRCW080518R2FKEA: RES, 18.2, 1%, 0.125 W, 0805; Manufacturer: Vishay-Dale; CompType: Resistor; Value: 18.2; Value_Code: 18R2; Tolerance_%: 1; Power_W: 0.125; Value2: 0.125W; VDC_V: 150; TempCo: 100 ppm/C; SizeArea_mm2: 2.5; SizeX_mm: 2; SizeY_mm: 1.25; SizeZ_mm: 1.45; EIA_Code: E96; U/M: EA; AEC Category: Q200
R6 R19 R74 = CRCW080510K0FKEA: RES, 10.0 k, 1%, 0.125 W, 0805; Manufacturer: Vishay-Dale; CompType: Resistor; Value: 10.0k; Res_ohm: 10000; Value_Code: 10k0; Tolerance_%: 1; Power_W: 0.125; Value2: 0.125W; VDC_V: 150; TempCo: 100 ppm/C; EIA_Code: E96; U/M: EA
R7 R8 = CSRN2512FK30L0: RES, 0.03, 1%, 2 W, 2512; Manufacturer: Stackpole Electronics Inc; CompType: Resistor; Value: 0.03; Value_Code: R030; Tolerance_%: 1; Power_W: 2; Value2: 2W; TempCo: 200 ppm/C; SizeArea_mm2: 20.16; SizeX_mm: 6.3; SizeY_mm: 3.2; SizeZ_mm: 0.71; EIA_Code: E96; U/M: EA; AEC Category: Q200
R11 R37 R39 R41 = CRCW060366K5FKEA: RES, 66.5 k, 1%, 0.1 W, 0603; Manufacturer: Vishay-Dale; CompType: Resistor; Value: 66.5k; Res_ohm: 66500; Value_Code: 66k5; Tolerance_%: 1; Power_W: 0.1; Value2: 0.1W; VDC_V: 75; TempCo: 100 ppm/C; EIA_Code: E96; U/M: EA
R14 = CMP-0022705-3: RES, 49.9 k, 1%, 0.1 W, AEC-Q200 Grade 0, 0603; Manufacturer: Panasonic; Power_W: 100mW; TempCo: 100 ppm/C; Value_Code: 49k9; U/M: EA; Value: 49.9k; EIA_Code: E96; SizeX_mm: 1.6; SizeY_mm: 0.8; SizeZ_mm: 1; Value2: 0.1W; SizeArea_mm2: 1.28; AEC Qualified: Y; VDC_V: 75V; AEC Grade: 0; AEC Category: Q200
R15 R16 = CRCW08052R20JNEA: RES, 2.2, 5%, 0.125 W, 0805; Manufacturer: Vishay-Dale; CompType: Resistor; Value: 2.2; Value_Code: 2R20; Tolerance_%: 5; Power_W: 0.125; Value2: 0.125W; VDC_V: 150; TempCo: 200 ppm/C; SizeArea_mm2: 2.5; SizeX_mm: 2; SizeY_mm: 1.25; SizeZ_mm: 1.45; EIA_Code: E24; U/M: EA; AEC Category: Q200; Green_Lifecycle: Active; Green_REACh: Passed
R20 = CMP-0018672-3: RES, 3.0 M, 5%, 0.25 W, AEC-Q200 Grade 0, 1206; Manufacturer: Vishay-Dale; Power_W: 250mW; TempCo: 200 ppm/C; Value_Code: 3M00; Value: 3.0Meg; EIA_Code: E24; Res_ohm: 3M; SizeX_mm: 3.2; SizeY_mm: 1.6; SizeZ_mm: 1.35; Value2: 0.25W; SizeArea_mm2: 5.12; AEC Qualified: Y; VDC_V: 200V; AEC Category: Q200; AEC Grade: 0
R21 R23 R33 R87 = CMP-0018647-3: RES, 2.7 M, 5%, 0.25 W, AEC-Q200 Grade 0, 1206; Manufacturer: Vishay-Dale; Power_W: 250mW; TempCo: 200 ppm/C; Value_Code: 2M70; Value: 2.7Meg; EIA_Code: E24; SizeX_mm: 3.2; SizeY_mm: 1.6; SizeZ_mm: 1.35; Value2: 0.25W; SizeArea_mm2: 5.12; AEC Qualified: Y; VDC_V: 200V; AEC Category: Q200; AEC Grade: 0
R24 R26 = CRCW060316K5FKEA: RES, 16.5 k, 1%, 0.1 W, 0603; Manufacturer: Vishay-Dale; CompType: Resistor; Value: 16.5k; Res_ohm: 16500; Value_Code: 16k5; Tolerance_%: 1; Power_W: 0.1; Value2: 0.1W; VDC_V: 75; TempCo: 100 ppm/C; EIA_Code: E96; U/M: EA
R27 R34 R46 R86 = CRCW08052M74FKEA: RES, 2.74 M, 1%, 0.125 W, 0805; Manufacturer: Vishay-Dale; CompType: Resistor; Value: 2.74Meg; Res_ohm: 2740000; Value_Code: 2M74; Tolerance_%: 1; Power_W: 0.125; Value2: 0.125W; VDC_V: 150; TempCo: 100 ppm/C; EIA_Code: E96; U/M: EA
R28 R77 = CRCW1206511KFKEA: RES, 511k ohm, 1%, 0.25W, 1206; Manufacturer: Vishay-Dale; CompType: Resistor; Res_ohm: 511000; Tolerance_%: 1; Power_W: 0.25; VDC_V: 200; TempCo: 100 ppm/C; EIA_Code: E96; U/M: EA
R30 = CRCW0603100RFKEA: RES, 100, 1%, 0.1 W, 0603; Manufacturer: Vishay-Dale; CompType: Resistor; Value: 100; Value_Code: 100R; Tolerance_%: 1; Power_W: 0.1; Value2: 0.1W; VDC_V: 75; TempCo: 100 ppm/C; EIA_Code: E96; U/M: EA
R35 = CRCW0603133KFKEA: RES, 133 k, 1%, 0.1 W, 0603; Manufacturer: Vishay-Dale; CompType: Resistor; Value: 133k; Res_ohm: 133000; Tolerance_%: 1; Power_W: 0.1; Value2: 0.1W; VDC_V: 75; TempCo: 100 ppm/C; EIA_Code: E96; U/M: EA
R42 = CRCW06037K50FKEA: RES, 7.50 k, 1%, 0.1 W, 0603; Manufacturer: Vishay-Dale; CompType: Resistor; Value: 7.50k; Res_ohm: 7500; Value_Code: 7k50; Tolerance_%: 1; Power_W: 0.1; Value2: 0.1W; VDC_V: 75; TempCo: 100 ppm/C; EIA_Code: E96; U/M: EA
R58 R59 = CRCW060310R0FKEAHP: RES, 10.0, 1%, 0.25 W, 0603; Manufacturer: Vishay-Dale; CompType: Resistor; Value: 10.0; Res_ohm: 10; Value_Code: 10R0; Tolerance_%: 1; Power_W: 0.25; Value2: 0.25W; VDC_V: 75; TempCo: 100 ppm/C; SizeArea_mm2: 1.28; SizeX_mm: 1.6; SizeY_mm: 0.8; EIA_Code: E96; U/M: EA; AEC Category: Q200; Green_Lifecycle: Active; Green_REACh: Passed
R75 = CMP-0022142-4: RES, 1.10 M, 1%, 0.1 W, AEC-Q200 Grade 0, 0603; Manufacturer: Vishay-Dale; Power_W: 100mW; TempCo: 100 ppm/C; Value_Code: 1M10; Value: 1.10Meg; EIA_Code: E96; Res_ohm: 1.1M; SizeX_mm: 1.6; SizeY_mm: 0.8; SizeZ_mm: 1; Value2: 0.1W; SizeArea_mm2: 1.28; AEC Qualified: Y; VDC_V: 75V; AEC Category: Q200; AEC Grade: 0
R76 = CRCW120649K9FKEA: RES, 49.9k ohm, 1%, 0.25W, 1206; Manufacturer: Vishay-Dale; CompType: Resistor; Res_ohm: 49900; Value_Code: 49k9; Tolerance_%: 1; Power_W: 0.25; VDC_V: 200; TempCo: 100 ppm/C; EIA_Code: E96; U/M: EA
R88 = CMP-0022686-2: RES, 124 k, 1%, 0.1 W, AEC-Q200 Grade 0, 0603; Manufacturer: Panasonic; Power_W: 100mW; TempCo: 100 ppm/C; U/M: EA; Value: 124k; EIA_Code: E96; SizeX_mm: 1.6; SizeY_mm: 0.8; SizeZ_mm: 1; Value2: 0.1W; SizeArea_mm2: 1.28; AEC Qualified: Y; VDC_V: 75V; AEC Grade: 0; AEC Category: Q200
R89 = CMP-0022659-4: RES, 95.3 k, 1%, 0.1 W, AEC-Q200 Grade 0, 0603; Manufacturer: Vishay-Dale; Power_W: 100mW; TempCo: 100 ppm/C; Value_Code: 95k3; Value: 95.3k; EIA_Code: E96; SizeX_mm: 1.6; SizeY_mm: 0.8; SizeZ_mm: 1; Value2: 0.1W; SizeArea_mm2: 1.28; AEC Qualified: Y; VDC_V: 75V; AEC Category: Q200; AEC Grade: 0
R90 = CRCW060382K5FKEA: RES, 82.5 k, 1%, 0.1 W, 0603; Manufacturer: Vishay-Dale; CompType: Resistor; Value: 82.5k; Res_ohm: 82500; Value_Code: 82k5; Tolerance_%: 1; Power_W: 0.1; Value2: 0.1W; VDC_V: 75; TempCo: 100 ppm/C; EIA_Code: E96; U/M: EA
RF1 = EMC2-47RKI: RES, 47, 10%, 2 W, Fusible, TH; Manufacturer: TT Electronics/IRC; SymbolCreator: a0412235; CompType: Fusible Resistor; Value: 47; Value_Code: 47R0; Tolerance_%: 10; Power_W: 2; Value2: 2W; TempCo: 100 ppm/C; U/M: EA
RV1 = S10K275E2: Varistor 275V RMS 10MM Radial, TH; Manufacturer: EPCOS Inc; SymbolCreator: a0412235
U1 U9 = CMP-0066947-1: 4A/4A Single Channel High-speed Low-side Gate Driver, DBV0005A (SOT-23-5); Alternate PartNumber: UCC27517DBVT; Alternate Manufacturer: Texas Instruments; Green_Lifecycle: Active; SizeAreaWB_mm2: 14.82; Green_REACh: Passed; U/M: EA; SizeZ_mm: 1.45; SizeX_mm: 2.8; SizeY_mm: 2.9; SizeArea_mm2: 8.12; CompType: IC
U3 = CMP-0065070-1: Natural Interleaving Transition Mode PFC Controller with Improved Light Load Efficiency, D0016A (SOIC-16); Alternate Manufacturer: Texas Instruments; SizeAreaWB_mm2: 95.2; U/M: EA; SizeZ_mm: 1.75; SizeX_mm: 6.0; SizeY_mm: 9.9; SizeArea_mm2: 59.4; CompType: IC
U13 = CMP-0073526-1: 36V, Low-Power, RRO, General-Purpose Operational Amplifier, DBV0005A (SOT-23-5); Alternate PartNumber: TLV171IDBVT; Alternate Manufacturer: Texas Instruments; SizeAreaWB_mm2: 14.82; U/M: EA; SizeZ_mm: 1.45; SizeX_mm: 2.8; SizeY_mm: 2.9; SizeArea_mm2: 8.12; CompType: IC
